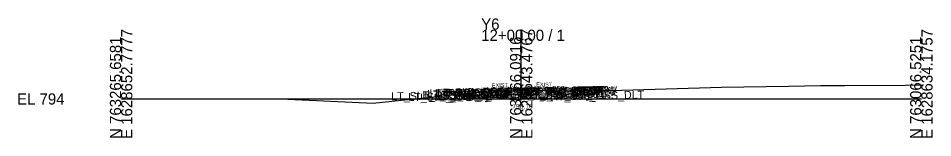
# Model space of a CAD drawing. Extents: x -26 to 203, y -10 to 6017.
# Drawn here: x -25.7 to 202.8, y 3990.3 to 4020.2 of the extents above; entities that cross this region are included whole.
import ezdxf

# ---------------------------------------------------------------- set-up
doc = ezdxf.new("R2010")
doc.units = 0
for name, color, linetype in [('Default', 7, 'Continuous'), ('Exist Cross Section Cell', 7, 'Continuous'), ('Exist XS Center Line Elevation Label', 7, 'Continuous'), ('Exist XS Ground Line', 7, 'Continuous'), ('Prop XS SE Text', 7, 'Continuous'), ('Scratch_Level_0', 7, 'Continuous')]:
    doc.layers.add(name, color=color, linetype=linetype)

msp = doc.modelspace()

# ---------------------------------------------------------------- linework, layer by layer
at = {"layer": 'Exist Cross Section Cell'}
for p, q in [((100, 4000), (100, 4017.32)), ((0, 4000), (100, 4000)), ((100, 4000), (200, 4000))]:
    msp.add_line(p, q, dxfattribs=at)
at = {"layer": 'Exist XS Ground Line'}
msp.add_lwpolyline([(41.7, 3999.94), (63.05, 3998.98), (63.63, 3999.04), (82.97, 4001.01), (87.91, 4001.55), (89.12, 4001.72), (91.39, 4001.81), (100, 4002.16), (100.51, 4002.18), (107.01, 4002.08), (110.9, 4002.02), (114.2, 4002.04), (125.12, 4002.18), (150.03, 4002.95), (166.83, 4003.21), (174.76, 4003.34), (180.82, 4003.32), (196, 4003.46), (200, 4003.5)], dxfattribs=at)

# ---------------------------------------------------------------- texts
at = {"layer": 'Default'}
msp.add_text('-', height=0.0001, dxfattribs=at).set_placement((0, 4000))
at = {"layer": 'Exist Cross Section Cell'}
for s, p in [('Y6', (90, 4017.32)), ('12+00.00 / 1', (90, 4014.52)), ('EL 794', (-26, 3998.6))]:
    msp.add_text(s, height=2.8, dxfattribs=at).set_placement(p)
for s, p in [('N 763265.6581', (0, 3990)), ('E 1628652.7777', (2.8, 3990)), ('N 763166.0916', (100, 3990)), ('E 1628643.4767', (102.8, 3990)), ('N 763066.5251', (200, 3990)), ('E 1628634.1757', (202.8, 3990))]:
    msp.add_text(s, height=2.8, rotation=90, dxfattribs=at).set_placement(p)
at = {"layer": 'Exist XS Center Line Elevation Label'}
msp.add_text('796.16', height=1.2, dxfattribs=at).set_placement((97.78, 3997.56))
at = {"layer": 'Prop XS SE Text'}
for rotation, p in [(2.2906, (92.69, 4002.87)), (359.4271, (103.74, 4003.12))]:
    msp.add_text('EXIST.', height=1, rotation=rotation, dxfattribs=at).set_placement(p)
at = {"layer": 'Scratch_Level_0'}
for s, p in [('LT_Sub_OSS_DLT', (67.53, 3999.64)), ('LT_Sub_Trench_Out', (71.79, 3999.46)), ('LT_PS3_Shelf_Out', (73.91, 3999.83)), ('LT_PV2_OEEOP_W', (76.56, 4000.22)), ('LT_PV3_OEEOP_W', (76.56, 3999.89)), ('LT_PV1_OEEOP_W', (77.13, 4000.36)), ('LT_PS3_OEOP', (78.66, 3999.93)), ('LT_PS2_OEOP', (79, 4000.27)), ('LT_PV1_OEEOP', (79.02, 4000.52)), ('LT_Sub_OEOT', (79.1, 3999.61)), ('LT_PV2_OEOT', (79.2, 4000.27)), ('LT_PV3_OEOT', (79.2, 3999.94)), ('LT_PV1_OEOT', (79.76, 4000.54)), ('LT_PS1_OEOP', (79.82, 4000.54)), ('RT_PV1_PGL_W', (89.86, 4000.83)), ('LT_PV1_PGL_W', (89.91, 4000.83)), ('Sub_PGL', (93.83, 4000.12)), ('PV2_PGL', (93.93, 4000.79)), ('PV3_PGL', (93.93, 4000.46)), ('PV1_PGL', (94.49, 4001.05)), ('RT_Sub_Trench_Out', (96.62, 3999.79)), ('RT_PS3_Shelf_Out', (98.06, 4000.16)), ('RT_PV2_OEEOP_W', (98.29, 4000.55)), ('RT_PV3_OEEOP_W', (98.29, 4000.22)), ('RT_PV1_OEEOP_W', (98.86, 4000.68)), ('RT_PV1_OEEOP', (100.75, 4000.85)), ('RT_Sub_OEOT', (101.05, 3999.93)), ('RT_PV2_OEOT', (101.15, 4000.6)), ('RT_PV3_OEOT', (101.15, 4000.27)), ('RT_PS2_OEOP', (101.47, 4000.6)), ('RT_PV1_OEOT', (101.71, 4000.86)), ('RT_PS1_OEOP', (101.78, 4000.87)), ('RT_PS3_OEOP', (101.81, 4000.26)), ('RT_Sub_OSS_DLT', (107.27, 3999.63))]:
    msp.add_text(s, height=2, rotation=1.1458, dxfattribs=at).set_placement(p)

doc.saveas('drawing.dxf')
